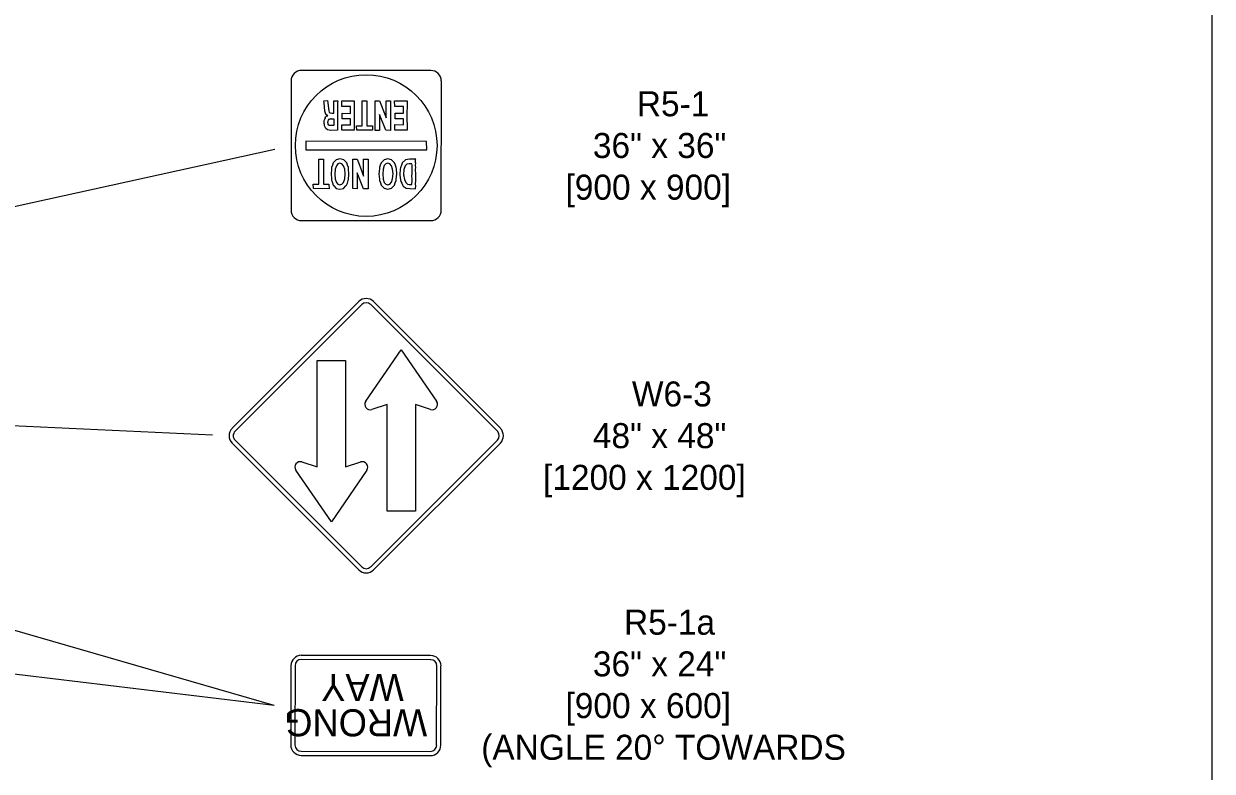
# Model space of a CAD drawing. Extents: x 49991.4 to 50021, y 49987.6 to 50011.4.
# Drawn here: x 50005.764 to 50008.615, y 50005.759 to 50007.552 of the extents above; entities that cross this region are included whole.
import ezdxf

# ---------------------------------------------------------------- set-up
doc = ezdxf.new("R2010")
doc.units = 0
for name, color, linetype in [('Level 1', 7, 'Continuous'), ('Level 2', 7, 'Continuous'), ('Level 3', 7, 'Continuous')]:
    doc.layers.add(name, color=color, linetype=linetype)

msp = doc.modelspace()

# ---------------------------------------------------------------- linework, layer by layer
at = {"layer": 'Level 1'}
for p, q in [((50006.7402, 50007.4397), (50006.4304, 50007.4399)), ((50006.4054, 50007.4149), (50006.4052, 50007.1047)), ((50006.7654, 50007.1045), (50006.7656, 50007.4147)), ((50006.4834, 50007.3669), (50006.4926, 50007.3673)), ((50006.484, 50007.3625), (50006.4834, 50007.3669)), ((50006.4926, 50007.3673), (50006.4954, 50007.3429)), ((50006.5076, 50007.3377), (50006.5078, 50007.3671)), ((50006.5078, 50007.3671), (50006.5168, 50007.3669)), ((50006.5168, 50007.3669), (50006.5166, 50007.3623)), ((50006.5264, 50007.3669), (50006.5564, 50007.3671)), ((50006.5266, 50007.3537), (50006.5264, 50007.3669)), ((50006.5564, 50007.3671), (50006.556, 50007.3585)), ((50006.5756, 50007.3071), (50006.5758, 50007.3669)), ((50006.5758, 50007.3669), (50006.587, 50007.3669)), ((50006.587, 50007.3669), (50006.5868, 50007.3073)), ((50006.6066, 50007.3539), (50006.6068, 50007.3669)), ((50006.6068, 50007.3669), (50006.6172, 50007.3669)), ((50006.6172, 50007.3669), (50006.6218, 50007.3547)), ((50006.6328, 50007.3539), (50006.633, 50007.3669)), ((50006.633, 50007.3669), (50006.6438, 50007.3669)), ((50006.6438, 50007.3669), (50006.6436, 50007.3539)), ((50006.6534, 50007.3669), (50006.6832, 50007.3671)), ((50006.6536, 50007.3537), (50006.6534, 50007.3669)), ((50006.6832, 50007.3671), (50006.6832, 50007.3585)), ((50006.484, 50007.3625), (50006.484, 50007.3625)), ((50006.484, 50007.3625), (50006.484, 50007.3625)), ((50006.4852, 50007.3531), (50006.484, 50007.3625)), ((50006.4854, 50007.3523), (50006.4852, 50007.3531)), ((50006.486, 50007.3423), (50006.4854, 50007.3523)), ((50006.486, 50007.3423), (50006.486, 50007.3421)), ((50006.4872, 50007.3377), (50006.486, 50007.3421)), ((50006.4876, 50007.3365), (50006.4872, 50007.3377)), ((50006.49, 50007.3331), (50006.4876, 50007.3365)), ((50006.4954, 50007.3429), (50006.4966, 50007.3395)), ((50006.4966, 50007.3395), (50006.4986, 50007.3381)), ((50006.4986, 50007.3381), (50006.503, 50007.3377)), ((50006.5026, 50007.3377), (50006.5076, 50007.3377)), ((50006.5166, 50007.3531), (50006.5164, 50007.3521)), ((50006.5164, 50007.3521), (50006.5166, 50007.2963)), ((50006.5166, 50007.3623), (50006.5166, 50007.3531)), ((50006.5474, 50007.3535), (50006.5266, 50007.3537)), ((50006.5278, 50007.3241), (50006.5278, 50007.3371)), ((50006.5278, 50007.3371), (50006.5474, 50007.3369)), ((50006.5474, 50007.3369), (50006.5474, 50007.3535)), ((50006.556, 50007.3585), (50006.556, 50007.3345)), ((50006.6066, 50007.2961), (50006.6066, 50007.3539)), ((50006.6218, 50007.3547), (50006.6328, 50007.3263)), ((50006.6328, 50007.3263), (50006.6328, 50007.3539)), ((50006.6436, 50007.3539), (50006.6438, 50007.3069)), ((50006.6744, 50007.3537), (50006.6536, 50007.3537)), ((50006.6548, 50007.3239), (50006.6548, 50007.3371)), ((50006.6548, 50007.3371), (50006.6744, 50007.3371)), ((50006.6744, 50007.3371), (50006.6744, 50007.3537)), ((50006.6832, 50007.3585), (50006.683, 50007.3345)), ((50006.4842, 50007.3125), (50006.4844, 50007.3153)), ((50006.4848, 50007.3105), (50006.4842, 50007.3125)), ((50006.4844, 50007.3153), (50006.4846, 50007.3197)), ((50006.4846, 50007.3197), (50006.4852, 50007.3213)), ((50006.4854, 50007.3069), (50006.4848, 50007.3105)), ((50006.4852, 50007.3213), (50006.4864, 50007.3249)), ((50006.4864, 50007.3251), (50006.4868, 50007.3259)), ((50006.4864, 50007.3251), (50006.4864, 50007.3249)), ((50006.4868, 50007.3259), (50006.4886, 50007.3285)), ((50006.4886, 50007.3285), (50006.491, 50007.3307)), ((50006.4928, 50007.3313), (50006.49, 50007.3331)), ((50006.491, 50007.3307), (50006.4928, 50007.3313)), ((50006.4934, 50007.3153), (50006.4942, 50007.3189)), ((50006.494, 50007.3125), (50006.4934, 50007.3153)), ((50006.494, 50007.3113), (50006.494, 50007.3125)), ((50006.4956, 50007.3089), (50006.494, 50007.3113)), ((50006.4942, 50007.3189), (50006.4944, 50007.3205)), ((50006.4944, 50007.3205), (50006.4958, 50007.3227)), ((50006.4972, 50007.3079), (50006.4956, 50007.3089)), ((50006.4958, 50007.3227), (50006.4976, 50007.3235)), ((50006.5, 50007.3077), (50006.4972, 50007.3079)), ((50006.4976, 50007.3235), (50006.5, 50007.3239)), ((50006.5052, 50007.3077), (50006.4996, 50007.3077)), ((50006.5008, 50007.3239), (50006.5, 50007.3239)), ((50006.5008, 50007.3239), (50006.5078, 50007.3237)), ((50006.5076, 50007.3077), (50006.5052, 50007.3077)), ((50006.5078, 50007.3237), (50006.5076, 50007.3077)), ((50006.527, 50007.2963), (50006.527, 50007.3095)), ((50006.527, 50007.3095), (50006.5474, 50007.3095)), ((50006.5474, 50007.3239), (50006.5278, 50007.3241)), ((50006.5474, 50007.3095), (50006.5474, 50007.3239)), ((50006.556, 50007.3345), (50006.556, 50007.3263)), ((50006.556, 50007.3263), (50006.5562, 50007.3047)), ((50006.5624, 50007.2963), (50006.5622, 50007.3073)), ((50006.5622, 50007.3073), (50006.5756, 50007.3071)), ((50006.5868, 50007.3073), (50006.6, 50007.3073)), ((50006.6, 50007.3073), (50006.6, 50007.2963)), ((50006.6322, 50007.2963), (50006.6172, 50007.3343)), ((50006.6172, 50007.3343), (50006.6174, 50007.2961)), ((50006.654, 50007.2965), (50006.654, 50007.3099)), ((50006.654, 50007.3099), (50006.6744, 50007.3095)), ((50006.6744, 50007.3239), (50006.6548, 50007.3239)), ((50006.6744, 50007.3095), (50006.6744, 50007.3239)), ((50006.683, 50007.3345), (50006.683, 50007.3263)), ((50006.683, 50007.3263), (50006.6832, 50007.3045)), ((50006.4856, 50007.3055), (50006.4854, 50007.3069)), ((50006.4886, 50007.3005), (50006.486, 50007.3053)), ((50006.4924, 50007.2977), (50006.4886, 50007.3005)), ((50006.4964, 50007.2965), (50006.4924, 50007.2977)), ((50006.5, 50007.2961), (50006.4964, 50007.2965)), ((50006.5166, 50007.2963), (50006.5, 50007.2961)), ((50006.5562, 50007.2963), (50006.527, 50007.2963)), ((50006.5562, 50007.3047), (50006.5562, 50007.2963)), ((50006.6, 50007.2963), (50006.5624, 50007.2963)), ((50006.6174, 50007.2961), (50006.6066, 50007.2961)), ((50006.6436, 50007.2961), (50006.6322, 50007.2963)), ((50006.6438, 50007.3069), (50006.6436, 50007.2961)), ((50006.6832, 50007.2963), (50006.654, 50007.2965)), ((50006.6832, 50007.3045), (50006.6832, 50007.2963)), ((50006.7302, 50007.2697), (50006.4404, 50007.2699)), ((50006.4404, 50007.2699), (50006.4404, 50007.2497)), ((50006.7304, 50007.2495), (50006.7302, 50007.2697)), ((50006.4404, 50007.2497), (50006.7304, 50007.2495)), ((50006.4716, 50007.1671), (50006.4716, 50007.2271)), ((50006.4716, 50007.2271), (50006.483, 50007.2271)), ((50006.483, 50007.2271), (50006.4828, 50007.1671)), ((50006.5132, 50007.2255), (50006.5076, 50007.2197)), ((50006.5222, 50007.2277), (50006.5132, 50007.2255)), ((50006.5312, 50007.2255), (50006.5222, 50007.2277)), ((50006.5368, 50007.2197), (50006.5312, 50007.2255)), ((50006.553, 50007.2137), (50006.553, 50007.2269)), ((50006.553, 50007.2269), (50006.5634, 50007.2269)), ((50006.5634, 50007.2269), (50006.568, 50007.2147)), ((50006.579, 50007.2137), (50006.579, 50007.2267)), ((50006.579, 50007.2267), (50006.59, 50007.2267)), ((50006.59, 50007.2267), (50006.5898, 50007.2139)), ((50006.628, 50007.2257), (50006.6226, 50007.2199)), ((50006.6372, 50007.2281), (50006.628, 50007.2257)), ((50006.6462, 50007.2257), (50006.6372, 50007.2281)), ((50006.6514, 50007.2199), (50006.6462, 50007.2257)), ((50006.6792, 50007.2253), (50006.6716, 50007.2185)), ((50006.6892, 50007.2267), (50006.6792, 50007.2253)), ((50006.7042, 50007.2269), (50006.6892, 50007.2267)), ((50006.7038, 50007.2253), (50006.7042, 50007.2269)), ((50006.7038, 50007.2185), (50006.7038, 50007.2253)), ((50006.502, 50007.2033), (50006.5008, 50007.1919)), ((50006.5022, 50007.2067), (50006.502, 50007.2033)), ((50006.504, 50007.2123), (50006.5022, 50007.2067)), ((50006.5022, 50007.2067), (50006.5022, 50007.2067)), ((50006.5042, 50007.2125), (50006.504, 50007.2123)), ((50006.5062, 50007.2179), (50006.5042, 50007.2125)), ((50006.5076, 50007.2197), (50006.5062, 50007.2183)), ((50006.5062, 50007.2183), (50006.5062, 50007.2179)), ((50006.5062, 50007.2179), (50006.5062, 50007.2179)), ((50006.511, 50007.2031), (50006.51, 50007.1913)), ((50006.5136, 50007.2111), (50006.511, 50007.2031)), ((50006.5172, 50007.2157), (50006.5136, 50007.2111)), ((50006.5222, 50007.2173), (50006.5172, 50007.2157)), ((50006.527, 50007.2159), (50006.5222, 50007.2173)), ((50006.531, 50007.2111), (50006.527, 50007.2159)), ((50006.5336, 50007.2029), (50006.531, 50007.2111)), ((50006.5346, 50007.1915), (50006.5336, 50007.2029)), ((50006.538, 50007.2183), (50006.5368, 50007.2197)), ((50006.5382, 50007.2179), (50006.538, 50007.2183)), ((50006.5384, 50007.2179), (50006.5382, 50007.2179)), ((50006.5402, 50007.2123), (50006.5384, 50007.2179)), ((50006.5426, 50007.2067), (50006.5402, 50007.2123)), ((50006.5428, 50007.2033), (50006.5426, 50007.2067)), ((50006.5426, 50007.2067), (50006.5426, 50007.2067)), ((50006.5438, 50007.1915), (50006.5428, 50007.2033)), ((50006.5428, 50007.2033), (50006.5428, 50007.2033)), ((50006.5528, 50007.1563), (50006.553, 50007.2137)), ((50006.5636, 50007.1941), (50006.5634, 50007.1559)), ((50006.5784, 50007.1561), (50006.5636, 50007.1941)), ((50006.568, 50007.2147), (50006.579, 50007.1861)), ((50006.579, 50007.1861), (50006.579, 50007.2137)), ((50006.5898, 50007.2139), (50006.5898, 50007.1669)), ((50006.617, 50007.2035), (50006.6158, 50007.1921)), ((50006.619, 50007.2129), (50006.617, 50007.2069)), ((50006.617, 50007.2069), (50006.617, 50007.2069)), ((50006.617, 50007.2069), (50006.617, 50007.2035)), ((50006.6212, 50007.2181), (50006.619, 50007.2129)), ((50006.619, 50007.2129), (50006.619, 50007.2129)), ((50006.6226, 50007.2199), (50006.6212, 50007.2185)), ((50006.6212, 50007.2185), (50006.6212, 50007.2181)), ((50006.6212, 50007.2181), (50006.6212, 50007.2181)), ((50006.6258, 50007.2033), (50006.625, 50007.1917)), ((50006.6286, 50007.2115), (50006.6258, 50007.2033)), ((50006.6322, 50007.2159), (50006.6286, 50007.2115)), ((50006.6372, 50007.2175), (50006.6322, 50007.2159)), ((50006.642, 50007.2161), (50006.6372, 50007.2175)), ((50006.6458, 50007.2113), (50006.642, 50007.2161)), ((50006.6482, 50007.2033), (50006.6458, 50007.2113)), ((50006.6496, 50007.1917), (50006.6482, 50007.2033)), ((50006.653, 50007.2185), (50006.6514, 50007.2199)), ((50006.653, 50007.2183), (50006.653, 50007.2185)), ((50006.6534, 50007.2183), (50006.653, 50007.2183)), ((50006.6552, 50007.2127), (50006.6534, 50007.2183)), ((50006.6572, 50007.2069), (50006.6552, 50007.2125)), ((50006.6574, 50007.2069), (50006.6572, 50007.2069)), ((50006.6576, 50007.2037), (50006.6574, 50007.2069)), ((50006.6578, 50007.2035), (50006.6576, 50007.2037)), ((50006.6588, 50007.1917), (50006.6578, 50007.2035)), ((50006.667, 50007.2033), (50006.6662, 50007.1899)), ((50006.6672, 50007.2059), (50006.667, 50007.2033)), ((50006.6696, 50007.2127), (50006.6672, 50007.2059)), ((50006.6714, 50007.2173), (50006.6696, 50007.2127)), ((50006.6716, 50007.2185), (50006.6714, 50007.2173)), ((50006.6756, 50007.2023), (50006.675, 50007.1895)), ((50006.6788, 50007.2113), (50006.6756, 50007.2023)), ((50006.6828, 50007.2149), (50006.6788, 50007.2113)), ((50006.6882, 50007.2161), (50006.6828, 50007.2149)), ((50006.695, 50007.2159), (50006.6882, 50007.2161)), ((50006.6952, 50007.2125), (50006.695, 50007.2159)), ((50006.6952, 50007.2059), (50006.6952, 50007.2125)), ((50006.6952, 50007.2033), (50006.6952, 50007.2057)), ((50006.6952, 50007.1899), (50006.6952, 50007.2033)), ((50006.704, 50007.2173), (50006.7038, 50007.2185)), ((50006.7038, 50007.2127), (50006.704, 50007.2173)), ((50006.704, 50007.2059), (50006.7038, 50007.2127)), ((50006.7038, 50007.2033), (50006.704, 50007.2059)), ((50006.704, 50007.1899), (50006.7038, 50007.2033)), ((50006.4584, 50007.1563), (50006.4582, 50007.1671)), ((50006.4582, 50007.1671), (50006.4716, 50007.1671)), ((50006.4828, 50007.1671), (50006.4958, 50007.1671)), ((50006.4958, 50007.1671), (50006.496, 50007.1561)), ((50006.5008, 50007.1919), (50006.5018, 50007.1787)), ((50006.5018, 50007.1787), (50006.5018, 50007.1787)), ((50006.5018, 50007.1787), (50006.502, 50007.1763)), ((50006.502, 50007.1763), (50006.5024, 50007.1753)), ((50006.5024, 50007.1753), (50006.5044, 50007.1699)), ((50006.5044, 50007.1699), (50006.5062, 50007.1645)), ((50006.51, 50007.1913), (50006.511, 50007.1791)), ((50006.511, 50007.1791), (50006.5136, 50007.1711)), ((50006.5136, 50007.1711), (50006.5174, 50007.1669)), ((50006.5174, 50007.1669), (50006.5222, 50007.1653)), ((50006.5222, 50007.1653), (50006.5268, 50007.1667)), ((50006.5268, 50007.1667), (50006.531, 50007.1713)), ((50006.531, 50007.1713), (50006.5336, 50007.1797)), ((50006.5336, 50007.1797), (50006.5346, 50007.1915)), ((50006.5382, 50007.1643), (50006.5402, 50007.1697)), ((50006.5402, 50007.1697), (50006.5422, 50007.1755)), ((50006.5422, 50007.1765), (50006.5424, 50007.1785)), ((50006.5422, 50007.1755), (50006.5422, 50007.1765)), ((50006.5424, 50007.1785), (50006.5438, 50007.1911)), ((50006.5438, 50007.1911), (50006.5438, 50007.1915)), ((50006.5898, 50007.1669), (50006.5898, 50007.1561)), ((50006.6158, 50007.1921), (50006.6168, 50007.1789)), ((50006.6168, 50007.1789), (50006.6168, 50007.1789)), ((50006.6168, 50007.1789), (50006.617, 50007.1767)), ((50006.617, 50007.1767), (50006.6174, 50007.1755)), ((50006.6174, 50007.1755), (50006.6192, 50007.1701)), ((50006.6192, 50007.1701), (50006.621, 50007.1647)), ((50006.621, 50007.1647), (50006.6214, 50007.1647)), ((50006.6214, 50007.1647), (50006.6214, 50007.1645)), ((50006.625, 50007.1915), (50006.6258, 50007.1793)), ((50006.6258, 50007.1793), (50006.6286, 50007.1713)), ((50006.6286, 50007.1713), (50006.6324, 50007.1671)), ((50006.6324, 50007.1671), (50006.637, 50007.1655)), ((50006.637, 50007.1655), (50006.6418, 50007.1669)), ((50006.6418, 50007.1669), (50006.646, 50007.1715)), ((50006.646, 50007.1715), (50006.6484, 50007.1799)), ((50006.6484, 50007.1799), (50006.6496, 50007.1917)), ((50006.653, 50007.1645), (50006.655, 50007.1699)), ((50006.655, 50007.1699), (50006.6572, 50007.1759)), ((50006.6572, 50007.1769), (50006.6574, 50007.1787)), ((50006.6572, 50007.1759), (50006.6572, 50007.1769)), ((50006.6574, 50007.1787), (50006.6588, 50007.1913)), ((50006.6588, 50007.1913), (50006.6588, 50007.1917)), ((50006.6662, 50007.1899), (50006.666, 50007.1883)), ((50006.666, 50007.1883), (50006.6678, 50007.1773)), ((50006.6678, 50007.1773), (50006.6686, 50007.1733)), ((50006.6686, 50007.1733), (50006.6704, 50007.1693)), ((50006.6704, 50007.1693), (50006.6724, 50007.1651)), ((50006.6724, 50007.1651), (50006.6732, 50007.1639)), ((50006.675, 50007.1901), (50006.6754, 50007.1885)), ((50006.675, 50007.1895), (50006.6768, 50007.1781)), ((50006.6768, 50007.1781), (50006.68, 50007.1709)), ((50006.68, 50007.1709), (50006.684, 50007.1673)), ((50006.684, 50007.1673), (50006.6886, 50007.1665)), ((50006.6886, 50007.1665), (50006.695, 50007.1665)), ((50006.695, 50007.1885), (50006.6952, 50007.1901)), ((50006.6952, 50007.1771), (50006.695, 50007.1883)), ((50006.695, 50007.1693), (50006.6952, 50007.1733)), ((50006.695, 50007.1665), (50006.695, 50007.1691)), ((50006.6952, 50007.1733), (50006.6952, 50007.1771)), ((50006.7038, 50007.1691), (50006.704, 50007.1733)), ((50006.7038, 50007.1651), (50006.7038, 50007.1691)), ((50006.704, 50007.1639), (50006.7038, 50007.1651)), ((50006.704, 50007.1883), (50006.704, 50007.1899)), ((50006.704, 50007.1773), (50006.704, 50007.1883)), ((50006.704, 50007.1733), (50006.704, 50007.1773)), ((50006.496, 50007.1561), (50006.4584, 50007.1563)), ((50006.5062, 50007.1645), (50006.5064, 50007.1643)), ((50006.5064, 50007.1643), (50006.5064, 50007.1641)), ((50006.5064, 50007.1641), (50006.5078, 50007.1627)), ((50006.5078, 50007.1627), (50006.5134, 50007.1569)), ((50006.5134, 50007.1569), (50006.5222, 50007.1549)), ((50006.5222, 50007.1549), (50006.531, 50007.1569)), ((50006.531, 50007.1569), (50006.5364, 50007.1627)), ((50006.5364, 50007.1627), (50006.5382, 50007.1643)), ((50006.5634, 50007.1559), (50006.5528, 50007.1563)), ((50006.5898, 50007.1561), (50006.5784, 50007.1561)), ((50006.6214, 50007.1645), (50006.6228, 50007.1629)), ((50006.6228, 50007.1629), (50006.6284, 50007.1571)), ((50006.6284, 50007.1571), (50006.637, 50007.1553)), ((50006.637, 50007.1553), (50006.6458, 50007.1573)), ((50006.6458, 50007.1573), (50006.6514, 50007.1629)), ((50006.6514, 50007.1629), (50006.653, 50007.1645)), ((50006.6732, 50007.1639), (50006.674, 50007.1625)), ((50006.674, 50007.1625), (50006.6814, 50007.1571)), ((50006.6814, 50007.1571), (50006.6906, 50007.1563)), ((50006.6906, 50007.1563), (50006.7038, 50007.1561)), ((50006.7038, 50007.1571), (50006.704, 50007.1623)), ((50006.7038, 50007.1561), (50006.7038, 50007.1571)), ((50006.704, 50007.1623), (50006.704, 50007.1639)), ((50006.4302, 50007.0797), (50006.7404, 50007.0797)), ((50006.2636, 50006.5815), (50006.5676, 50006.8855)), ((50006.603, 50006.8855), (50006.9072, 50006.5815)), ((50006.2708, 50006.5745), (50006.5748, 50006.8785)), ((50006.596, 50006.8785), (50006.9, 50006.5745)), ((50006.584, 50006.6465), (50006.6692, 50006.7701)), ((50006.6692, 50006.7701), (50006.7542, 50006.6465)), ((50006.4676, 50006.4889), (50006.4676, 50006.7445)), ((50006.4676, 50006.7445), (50006.5356, 50006.7445)), ((50006.5356, 50006.7445), (50006.5356, 50006.4889)), ((50006.6352, 50006.6385), (50006.5988, 50006.6269)), ((50006.6352, 50006.3831), (50006.6352, 50006.6385)), ((50006.7396, 50006.6269), (50006.7032, 50006.6385)), ((50006.7032, 50006.6385), (50006.7032, 50006.3831)), ((50006.5676, 50006.2421), (50006.2636, 50006.5461)), ((50006.5748, 50006.2491), (50006.2708, 50006.5533)), ((50006.9, 50006.5533), (50006.596, 50006.2491)), ((50006.9072, 50006.5461), (50006.603, 50006.2421)), ((50006.5016, 50006.3575), (50006.4164, 50006.4813)), ((50006.4312, 50006.5009), (50006.4676, 50006.4889)), ((50006.5868, 50006.4813), (50006.5016, 50006.3575)), ((50006.5356, 50006.4889), (50006.572, 50006.5009)), ((50006.7032, 50006.3831), (50006.6352, 50006.3831)), ((50006.7395, 50006.0364), (50006.4293, 50006.0369)), ((50006.7399, 50006.0263), (50006.4299, 50006.0267)), ((50006.4045, 50006.0121), (50006.4047, 50005.8219)), ((50006.4149, 50006.0123), (50006.4143, 50005.8221)), ((50006.7541, 50005.8216), (50006.7543, 50006.0111)), ((50006.7643, 50005.8213), (50006.7643, 50006.0114)), ((50006.4291, 50005.8072), (50006.7393, 50005.8066)), ((50006.4295, 50005.797), (50006.7391, 50005.7964))]:
    msp.add_line(p, q, dxfattribs=at)
msp.add_lwpolyline([(50008.6146, 50011.2628), (50000.3356, 50011.2628), (50000.3356, 50000.0624), (50008.6146, 50000.0624)], close=True, dxfattribs=at)
msp.add_circle((50006.5852, 50007.2597), 0.1699, dxfattribs=at)
for centre, radius, start, end in [((50006.4301, 50007.4148), 0.025, 89.9905, 179.9905), ((50006.7402, 50007.4147), 0.025, 359.9905, 89.9905), ((50006.43, 50007.1046), 0.025, 179.9905, 269.9905), ((50006.7402, 50007.1046), 0.025, 269.9905, 359.9905), ((50006.5853, 50006.8678), 0.025, 45, 135), ((50006.5853, 50006.8678), 0.015, 45, 135), ((50006.5946, 50006.639), 0.0129, 145.5849, 216.7163), ((50006.5946, 50006.639), 0.0129, 216.7194, 287.9582), ((50006.7435, 50006.639), 0.0129, 252.0418, 323.2776), ((50006.7435, 50006.639), 0.0129, 323.2806, 34.5194), ((50006.2812, 50006.5637), 0.025, 134.9998, 225), ((50006.2812, 50006.5637), 0.015, 134.9998, 225), ((50006.8893, 50006.5637), 0.015, 315, 45), ((50006.8893, 50006.5637), 0.025, 315, 45), ((50006.4271, 50006.4885), 0.0129, 143.2806, 214.5194), ((50006.4271, 50006.4885), 0.0129, 72.0418, 143.2776), ((50006.5759, 50006.4885), 0.0129, 36.7194, 107.9582), ((50006.5759, 50006.4885), 0.0129, 325.585, 36.7163), ((50006.5853, 50006.2597), 0.025, 225.0004, 315), ((50006.5853, 50006.2597), 0.015, 225.0004, 315), ((50006.4297, 50006.0121), 0.025, 89.8987, 179.8987), ((50006.4297, 50006.0121), 0.015, 89.8987, 179.8987), ((50006.7397, 50006.0116), 0.025, 359.8987, 89.8987), ((50006.7397, 50006.0116), 0.015, 359.8987, 89.8987), ((50006.4293, 50005.8221), 0.025, 179.8987, 269.8987), ((50006.4293, 50005.8221), 0.015, 179.8987, 269.8987), ((50006.7393, 50005.8216), 0.025, 269.8987, 359.8987), ((50006.7393, 50005.8216), 0.015, 269.8987, 359.8987)]:
    msp.add_arc(centre, radius, start, end, dxfattribs=at)
at = {"layer": 'Level 3'}
for p, q in [((50003.9122, 50006.711), (50006.3662, 50007.2512)), ((50003.9236, 50006.6717), (50006.2162, 50006.5656)), ((50006.3646, 50005.917), (50004.6718, 50006.4062)), ((50006.3646, 50005.917), (50004.0718, 50006.1913))]:
    msp.add_line(p, q, dxfattribs=at)

# ---------------------------------------------------------------- texts
at = {"layer": 'Level 1'}
for s, p in [('WAY', (50006.6755, 50005.9921)), ('WRONG', (50006.7317, 50005.9074))]:
    msp.add_text(s, height=0.065, rotation=179.8987, dxfattribs=at).set_placement(p)
at = {"layer": 'Level 2'}
for s, p in [('R5-1', (50007.2344, 50007.3299)), ('36" x 36"', (50007.1289, 50007.2298)), ('[900 x 900]', (50007.0633, 50007.1298))]:
    msp.add_text(s, height=0.06, rotation=0.0174, dxfattribs=at).set_placement(p)
for s, p in [('W6-3', (50007.2226, 50006.6339)), ('48" x 48"', (50007.1289, 50006.5339)), ('[1200 x 1200]', (50007.0094, 50006.4339)), ('R5-1a', (50007.2036, 50006.0865)), ('36" x 24"', (50007.1289, 50005.9865)), ('[900 x 600]', (50007.0633, 50005.8865)), ('(ANGLE 20° TOWARDS', (50006.8611, 50005.7865))]:
    msp.add_text(s, height=0.06, dxfattribs=at).set_placement(p)

doc.saveas('drawing.dxf')
